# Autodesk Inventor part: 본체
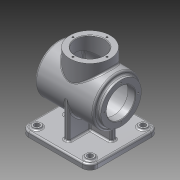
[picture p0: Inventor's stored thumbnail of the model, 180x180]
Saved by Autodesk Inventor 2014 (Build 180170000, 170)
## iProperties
Created: 2015-07
Part Number: 본체
Material: 알루미늄 6061
Document SubType Name: Modeling
Designer: net
Mass: 1277.64 g
Surface Area: 1267.59 cm^2
Volume: 471.454 cm^3
Density: 2.71 g/cm^3
Appearance: 알루미늄 - 평지
Author: net
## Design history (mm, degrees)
sketch "스케치1"
  geometry: L1 (-58.5, 0)-(58.5, 0); L2 (-58.5, 0)-(-58.5, 38); L3 (-58.5, 38)-(-51.5, 38); L4 (-51.5, 38)-(-51.5, 45); L5 (-51.5, 45)-(58.5, 45); L6 (58.5, 45)-(58.5, 0); L7 (-58.5, 27)-(-44.5, 27); L8 (-44.5, 27)-(-44.5, 40); L9 (-44.5, 40)-(51.5, 40); L10 (51.5, 40)-(51.5, 0); 2 further points
  constraints: 20 end point, 5 perpendicular, 4 parallel, 2 point on line, 1 coincident, 1 horizontal, 1 midpoint
  dimensions: "d1" = 76 diameter of L3 L1; "d2" = 90 diameter of L5 L1; "d3" = 7 distance of L2.end L3.end; "d4" = 54 diameter of L7 L1; "d5" = 7 distance between parallel lines of L6 L10; "d6" = 14 distance of L7.start L7.end; "d7" = 80 diameter of L9 L1; "d18" = 117 distance between parallel lines of L6 L2
revolve "회전1" sketch "스케치1" stored, may be unused: angle "d8" = 90 deg
node "작업 평면1"
sketch "스케치2"
  geometry: L1 (-65, -65)-(65, -65); L2 (65, -65)-(65, 65); L3 (65, 65)-(-65, 65); L4 (-65, 65)-(-65, -65); L5 (58.5, -45)-(58.5, 45) reference; 1 further point
  constraints: 8 end point, 2 parallel, 1 horizontal, 1 perpendicular
  dimensions: "d10" = 130 distance of L3.end L1.start; "d11" = 130 distance of L1.start L1.end
extrude "돌출1" join sketch "스케치2" distance "d14" = 10; taper "d15" = 0 deg
sketch "스케치5"
  geometry: L1 (-68, -65)-(-78, -65) reference; L2 (-78, -65)-(-78, 65) reference; L3 (-78, 65)-(-68, 65) reference; L4 (-68, 65)-(-68, -65) reference; L5 (0, 45)-(-68, 45); L6 (-68, 45)-(-68, 1.271); L7 (-68, 1.271)-(-42.748, 1.271); L8 (-42.748, 1.271)-(-35.553, 23.136); L9 (-35.553, 23.136)-(-24.669, 33.556); L10 (-24.669, 33.556)-(0, 45); C1 r 40 at (0, 0) reference; A1 r 45 centre (0, 0) between (-45, 0) and (0, 45) reference; 1 further point
  constraints: 12 end point, 2 point on line, 1 perpendicular, 1 point on circle, 1 tangent
extrude "돌출3" join sketch "스케치5" stored distance "d21" = 10; taper "d22" = 0 deg
node "작업 평면2"
sketch "스케치6"
  geometry: C1 r 38 at (0, 0); 1 further point
  constraints: 1 centre point, 1 coincident
  dimensions: "d24" = 76 diameter of C1
extrude "돌출4" join sketch "스케치6" stored distance "d25" = 10; taper "d26" = 0 deg
sketch "스케치7"
  geometry: C1 r 38 at (0, 0) reference; C2 r 27 at (0, 0)
  constraints: 1 centre point, 1 coincident
  dimensions: "d27" = 54 diameter of C2
extrude "돌출5" cut sketch "스케치7" stored distance "d28" = 10; taper "d29" = 0 deg
sketch "스케치8"
  geometry: C1 r 7.5 at (-50, 50); 1 further point
  constraints: 1 centre point
  dimensions: "d30" = 15 diameter of C1; "d31" = 50 horizontal distance of point (0, 0) C1.centre; "d32" = 50 horizontal distance of point (0, 0) C1.centre
extrude "돌출6" join sketch "스케치8" distance "d33" = 3; taper "d34" = 0 deg
sketch "스케치9"
  geometry: C1 r 7.5 at (0, 0) reference; C2 r 5 at (0, 0); 1 further point
  constraints: 1 centre point, 1 coincident
  dimensions: "d41" = 10 diameter of C2
extrude "돌출7" cut sketch "스케치9" distance "d42" = 13; taper "d43" = 0 deg
sketch "스케치10" dims "d50" = 64
  geometry: C1 r 27 at (0, 0) reference; C2 r 38 at (0, 0) reference; 2 further points
  constraints: 2 vertical alignment, 1 coincident, 2 other
hole "구멍1" sketch "스케치10" at (0, 32) diameter "d51" = 3.242; stored, may be unused: countersink angle "d55" = 90 deg, drill point angle "d57" = 118 deg; dims "d52" = 8, "d53" = 4, "d54" = 2, "d56" = 10
sketch "스케치11" dims "d61" = 64
  geometry: C1 r 27 at (0, 0) reference; C2 r 38 at (0, 0) reference; 2 further points
  constraints: 2 horizontal alignment, 1 coincident, 2 other
hole "구멍2" sketch "스케치11" at (32, 0) diameter "d62" = 3.242; stored, may be unused: countersink angle "d66" = 90 deg, drill point angle "d68" = 118 deg; dims "d63" = 8, "d64" = 4, "d65" = 2, "d67" = 10
fillet "모깎기1" dims "d72" = 15
sketch "스케치12"
  geometry: L1 (5, -45)-(-5, -45) reference; L2 (-45, 5)-(-45, -5); L3 (-45, -5)-(45, -5); L4 (45, -5)-(45, 5); L5 (45, 5)-(-45, 5); 1 further point
  constraints: 8 end point, 2 parallel, 2 perpendicular
  dimensions: "d74" = 10 distance of L2.start L2.end; "d75" = 5 distance from line of point (0, 0) L5; "d76" = 90 distance between parallel lines of L4 L2; "d77" = 45 distance from line of L2 point (0, 0)
extrude "돌출8" join sketch "스케치12" stored distance "d78" = 13; taper "d79" = 0 deg
fillet "모깎기2" dims "d80" = 3
fillet "모깎기3" dims "d81" = 3
sketch "스케치13"
  geometry: C1 r 42 at (0, 0) reference; 1 further point
  constraints: 1 coincident, 1 other
feature "엠보싱1" sketch "스케치13" dims "d82" = 0.5, "d83" = 0
chamfer "모따기1" distance "d84" = 1; stored, may be unused: second distance "d85" = 2, angle "d86" = 45 deg
fillet "모깎기4" dims "d87" = 3
node "솔리드1"
mirror "대칭1"
pattern_linear "직사각형 패턴1" dims "d37" = 100
pattern_linear "직사각형 패턴2" dims "d46" = 100
pattern_circular "원형 패턴1" dims angle "d59" = 360 deg
pattern_circular "원형 패턴2" dims angle "d70" = 360 deg
node "절단 모서리 투영2"
other parameters: "d9" = -78
